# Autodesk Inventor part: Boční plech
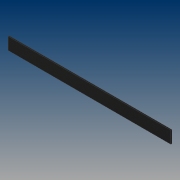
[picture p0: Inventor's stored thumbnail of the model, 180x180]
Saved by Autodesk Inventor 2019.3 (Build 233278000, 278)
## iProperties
Created: 2019-02
Part Number: Boční plech
Material: Ocel, měkká, svařovaná
Document SubType Name: Modeling
Designer: B-hon
Density: 7.85 g/cm^3
Appearance: Černý – litý
Author: B-hon
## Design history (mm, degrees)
sketch "Náčrt1"
  geometry: L1 (0, 0)-(1210, 0); L2 (1210, 0)-(1210, 90); L3 (1210, 90)-(0, 90); L4 (0, 90)-(0, 0)
  constraints: 8 end point, 2 parallel, 1 horizontal, 1 perpendicular
  dimensions: "d0" = 1210 distance of L3.end L2.end; "d1" = 90 distance of L2.end L1.end
extrude "Vysunutí1" new body sketch "Náčrt1" distance "d2" = 8; taper "d3" = 0 deg
node "Těleso1"
